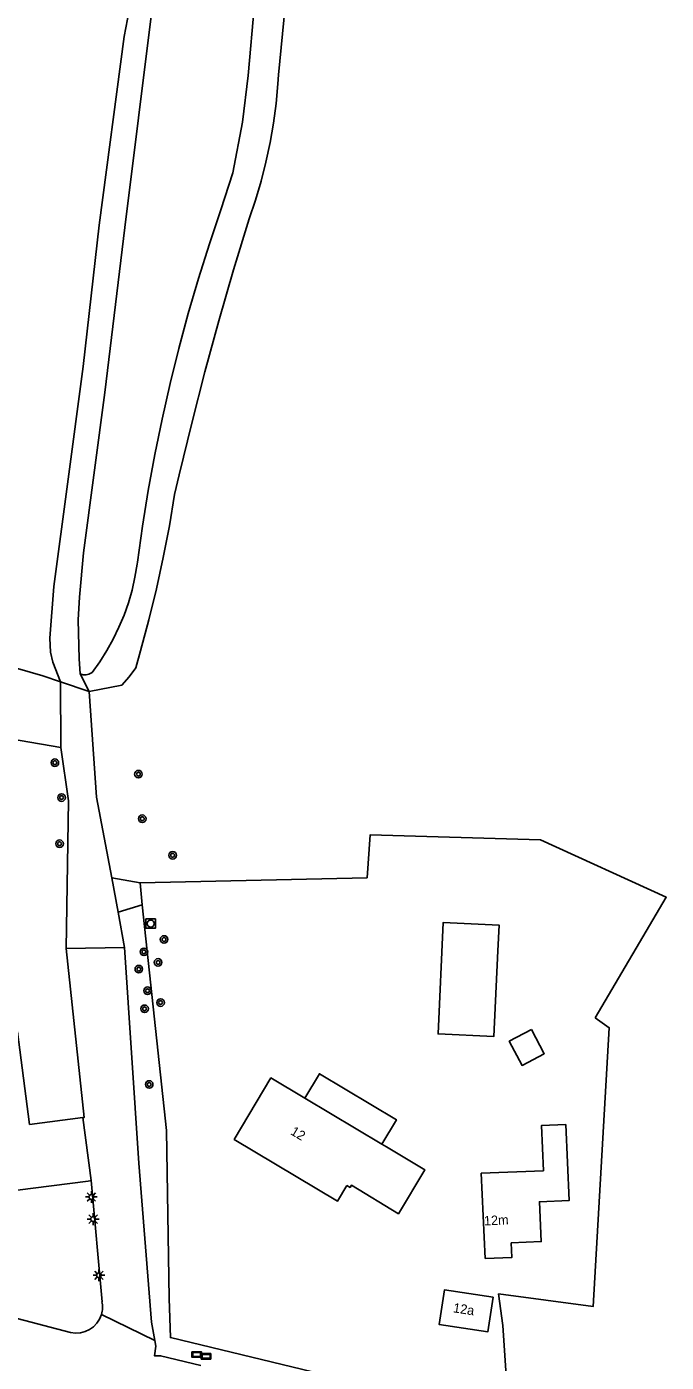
# Model space of a CAD drawing. Extents: x 137000 to 140001, y 403500 to 406000.
# Drawn here: x 138474.3 to 138542, y 405655.3 to 405796.6 of the extents above; entities that cross this region are included whole.
import ezdxf

# ---------------------------------------------------------------- set-up
doc = ezdxf.new("R2010")
doc.units = 0
for name, color, linetype in [('gg-afsc-erfafscheiding', 7, 'Continuous'), ('gg-anno-huisnummerreeks BGT', 7, 'Continuous'), ('gg-bbg-bijgebouw', 7, 'Continuous'), ('gg-bbg-hoofdgebouw', 7, 'Continuous'), ('gg-bbg-luifel en loopbrug', 7, 'Continuous'), ('gg-knt-verharding', 7, 'Continuous'), ('gt-grn-groengrens', 7, 'Continuous'), ('gt-grn-groengrens NZ', 7, 'Continuous'), ('gt-grn-weggrens', 7, 'Continuous'), ('gt-symb-boom', 7, 'Continuous'), ('gt-symb-informatiebord', 7, 'Continuous'), ('gt-symb-lichtmast', 7, 'Continuous'), ('gt-symb-rioolschacht', 7, 'Continuous'), ('gx-grn-maaiveld', 7, 'Continuous')]:
    doc.layers.add(name, color=color, linetype=linetype)

# ---------------------------------------------------------------- blocks, each defined once
blk = doc.blocks.new('gt0-IBORD')
at = {"layer": 'gt-symb-informatiebord'}
blk.add_lwpolyline([(-0.5, 0.29), (-0.5, -0.29), (0.5, -0.29), (0.5, 0.29), (-0.5, 0.29)], dxfattribs=at)
blk.add_lwpolyline([(-0.42, -0.21), (0.42, -0.21), (0.42, 0.21), (-0.42, 0.21)], close=True, dxfattribs=at)
blk = doc.blocks.new('gt0-LMAST')
at = {"layer": 'gt-symb-lichtmast'}
for p, q in [((-0.18, 0.17), (-0.45, 0.44)), ((-0.01, 0.25), (-0.01, 0.62)), ((0.17, 0.17), (0.44, 0.44)), ((-0.26, 0), (-0.63, 0)), ((-0.18, -0.18), (-0.45, -0.45)), ((-0.01, -0.25), (-0.01, -0.63)), ((0.44, -0.45), (0.17, -0.18)), ((0.24, 0), (0.62, 0))]:
    blk.add_line(p, q, dxfattribs=at)
blk.add_circle((-0.01, 0), 0.25, dxfattribs=at)
blk = doc.blocks.new('gt0-BOOM')
at = {"layer": 'gt-symb-boom'}
for radius in [0.4, 0.2]:
    blk.add_circle((0, 0), radius, dxfattribs=at)
blk = doc.blocks.new('gt0-RS')
at = {"layer": 'gt-symb-rioolschacht'}
blk.add_lwpolyline([(-0.5, -0.5), (0.5, -0.5), (0.5, 0.5), (-0.5, 0.5)], close=True, dxfattribs=at)
blk.add_circle((0, 0), 0.375, dxfattribs=at)

msp = doc.modelspace()

# ---------------------------------------------------------------- linework, layer by layer
at = {"layer": 'gg-afsc-erfafscheiding'}
msp.add_line((138486.33, 405706.01), (138486.54, 405703.68), dxfattribs=at)
for points in [[(138431.55, 405686.42), (138430.73, 405691.32), (138432.04, 405696.3), (138433.12, 405700.81), (138433.36, 405702.15), (138433.12, 405705.77), (138432.66, 405708.47), (138432.93, 405711.45), (138433.97, 405715.93), (138437.22, 405720.74), (138440.96, 405723.28), (138453.34, 405724.56), (138477.96, 405720.34)], [(138534.45, 405691.71), (138541.98, 405704.49), (138528.68, 405710.57), (138510.65, 405711.08), (138510.33, 405706.55), (138486.33, 405706.01)], [(138486.54, 405703.68), (138489.13, 405679.79), (138489.39, 405662.02), (138489.53, 405657.88), (138510.97, 405652.71)], [(138534.45, 405691.71), (138535.94, 405690.68), (138534.23, 405661.15), (138524.24, 405662.49)], [(138525.36, 405649.07), (138524.7, 405659.15), (138524.24, 405662.49)]]:
    msp.add_lwpolyline(points, dxfattribs=at)
at = {"layer": 'gg-bbg-bijgebouw'}
for points in [[(138524.16, 405698.8), (138523.75, 405689.75), (138517.85, 405690.02), (138518.39, 405701.82), (138524.29, 405701.55), (138524.16, 405698.8)], [(138527.71, 405690.49), (138529.07, 405687.93), (138526.73, 405686.68), (138525.37, 405689.24), (138527.71, 405690.49)]]:
    msp.add_lwpolyline(points, dxfattribs=at)
at = {"layer": 'gg-bbg-hoofdgebouw'}
for p, q in [((138511.9, 405678.35), (138503.75, 405683.22)), ((138480.27, 405681.18), (138481.15, 405674.49))]:
    msp.add_line(p, q, dxfattribs=at)
for points in [[(138481.15, 405674.49), (138480.83, 405674.45), (138469.46, 405672.97), (138469.72, 405670.99), (138465.26, 405670.4), (138465, 405672.39), (138456.09, 405671.22), (138453.9, 405687.96), (138454.75, 405688.07), (138454.63, 405688.96), (138454.33, 405688.93), (138453.54, 405694.97), (138465.4, 405696.52), (138472.02, 405697.38), (138472.81, 405691.33), (138471.87, 405691.2), (138472.02, 405690.06), (138473.35, 405690.24), (138474.63, 405680.44), (138480.27, 405681.18)], [(138503.75, 405683.22), (138500.17, 405685.36), (138496.28, 405678.86), (138507.22, 405672.33), (138508.2, 405673.97)], [(138522.82, 405666.24), (138525.66, 405666.37), (138525.59, 405667.89), (138528.76, 405668.03), (138528.56, 405672.26), (138531.71, 405672.4), (138531.35, 405680.43), (138528.79, 405680.33), (138528.98, 405675.53), (138522.41, 405675.27), (138522.82, 405666.24)], [(138508.2, 405673.97), (138508.54, 405673.77), (138508.68, 405674.01), (138513.65, 405670.99), (138516.43, 405675.64), (138512.39, 405678.06), (138511.9, 405678.35)], [(138523.66, 405662.14), (138518.52, 405662.92), (138517.95, 405659.27), (138523.1, 405658.48), (138523.66, 405662.14)]]:
    msp.add_lwpolyline(points, dxfattribs=at)
at = {"layer": 'gg-bbg-luifel en loopbrug'}
msp.add_lwpolyline([(138511.9, 405678.35), (138513.44, 405680.93), (138505.29, 405685.8), (138503.75, 405683.22)], dxfattribs=at)
at = {"layer": 'gg-knt-verharding'}
for p, q in [((138480.94, 405726.27), (138477.92, 405727.28)), ((138480, 405728.14), (138480.94, 405726.27)), ((138484, 405702.9), (138483.32, 405706.55)), ((138484.69, 405699.18), (138484, 405702.9)), ((138484.69, 405699.18), (138478.49, 405699.08)), ((138481.15, 405674.49), (138482.3, 405661.67)), ((138472.67, 405660.08), (138478.98, 405658.41)), ((138482.23, 405660.32), (138487.89, 405657.57))]:
    msp.add_line(p, q, dxfattribs=at)
for points in [[(138480.27, 405681.18), (138480.42, 405681.19), (138478.49, 405699.08)], [(138487.89, 405657.57), (138487.53, 405659.52), (138486.2, 405676.34), (138484.69, 405699.18)], [(138492.74, 405654.93), (138488.49, 405655.96), (138487.85, 405655.94), (138488, 405656.95), (138487.89, 405657.57)]]:
    msp.add_lwpolyline(points, dxfattribs=at)
for centre, radius, start, end in [((138479.57, 405661.12), 2.78, 343.3166, 11.5167), ((138479.58, 405661.12), 2.77, 257.4446, 343.2739)]:
    msp.add_arc(centre, radius, start, end, dxfattribs=at)
at = {"layer": 'gt-grn-groengrens'}
msp.add_lwpolyline([(138373.64, 405757.58), (138476.03, 405727.91), (138477.92, 405727.28)], dxfattribs=at)
at = {"layer": 'gt-grn-groengrens NZ'}
msp.add_line((138483.32, 405706.55), (138486.33, 405706.01), dxfattribs=at)
at = {"layer": 'gt-grn-weggrens'}
msp.add_line((138484, 405702.9), (138486.54, 405703.68), dxfattribs=at)
at = {"layer": 'gx-grn-maaiveld'}
msp.add_line((138477.96, 405720.34), (138477.92, 405727.28), dxfattribs=at)
for points in [[(138477.92, 405727.28), (138477.08, 405729.38), (138476.86, 405730.43), (138476.77, 405731.92), (138477.19, 405737.4), (138478.65, 405748.23), (138480.29, 405760.66), (138482.01, 405775.64), (138484.64, 405795.61), (138485.69, 405801.13), (138489.95, 405817.8), (138494.25, 405836.19), (138500.42, 405863.55), (138505.03, 405882.67), (138509.48, 405899), (138514.17, 405914.96), (138519.47, 405934.58), (138526.93, 405959.19), (138532.1, 405977.85), (138534.11, 405985.54), (138537.9, 405998.75), (138538.28, 406000)], [(138480, 405728.14), (138479.89, 405729.72), (138479.79, 405733.87), (138479.91, 405736.27), (138480.33, 405740.95), (138482.58, 405757.92), (138484.7, 405775.38), (138487.6, 405798.61), (138492.81, 405819.24), (138496.9, 405837.24), (138501.92, 405857.44), (138503.46, 405865.82), (138504.47, 405870.66), (138505.66, 405874.92), (138510.58, 405893.66), (138518.46, 405921.11), (138524.63, 405942.49), (138529.73, 405959.98), (138533.05, 405971.51), (138535.42, 405980.71), (138538.64, 405993.55), (138540.61, 406000)], [(138480.94, 405726.27), (138484.41, 405726.94), (138485.18, 405727.81), (138485.86, 405728.79), (138486.37, 405730.58), (138487.25, 405733.86), (138488.05, 405737.15), (138488.77, 405740.46), (138489.42, 405743.79), (138489.98, 405747.13), (138490.46, 405749.2), (138491.79, 405754.66), (138493.19, 405760.1), (138494.66, 405765.51), (138496.22, 405770.91), (138497.85, 405776.29), (138498.52, 405778.27), (138499.12, 405780.28), (138499.63, 405782.32), (138500.07, 405784.37), (138500.43, 405786.43), (138500.71, 405788.51), (138500.91, 405790.6), (138500.98, 405791.56), (138502.27, 405804.97)], [(138480, 405728.14), (138480.3, 405728.05), (138480.61, 405728.04), (138480.91, 405728.11), (138481.18, 405728.25), (138481.24, 405728.29), (138482.05, 405729.42), (138482.8, 405730.6), (138483.48, 405731.81), (138484.09, 405733.07), (138484.63, 405734.35), (138485.09, 405735.67), (138485.48, 405737.01), (138485.78, 405738.36), (138486.01, 405739.74), (138486.04, 405739.96), (138486.58, 405743.77), (138487.19, 405747.56), (138487.88, 405751.34), (138488.65, 405755.11), (138489.49, 405758.86), (138490.42, 405762.59), (138491.42, 405766.3), (138492.5, 405769.99), (138493.65, 405773.65), (138494.88, 405777.26), (138496.15, 405781.16), (138497.16, 405786.53), (138497.77, 405791.47), (138498.42, 405799.02)], [(138483.32, 405706.55), (138481.73, 405715.1), (138480.94, 405726.27)], [(138478.49, 405699.08), (138478.76, 405714.68), (138477.96, 405720.34)]]:
    msp.add_lwpolyline(points, dxfattribs=at)

# ---------------------------------------------------------------- block references
at = {"layer": 'gt-symb-boom'}
for p in [(138477.31, 405718.73), (138486.15, 405717.52), (138478.02, 405715.04), (138486.56, 405712.8), (138477.81, 405710.16), (138489.77, 405708.93), (138488.86, 405700.02), (138486.73, 405698.71), (138488.23, 405697.59), (138486.19, 405696.88), (138487.11, 405694.59), (138488.49, 405693.34), (138486.8, 405692.68), (138487.29, 405684.67)]:
    msp.add_blockref('gt0-BOOM', p, dxfattribs=at)
at = {"layer": 'gt-symb-informatiebord'}
for p in [(138492.31, 405656.09), (138493.3, 405655.89)]:
    msp.add_blockref('gt0-IBORD', p, dxfattribs=at)
at = {"layer": 'gt-symb-lichtmast'}
for p in [(138481.18, 405672.76), (138481.37, 405670.42), (138481.98, 405664.47)]:
    msp.add_blockref('gt0-LMAST', p, dxfattribs=at)
at = {"layer": 'gt-symb-rioolschacht'}
msp.add_blockref('gt0-RS', (138487.45, 405701.7), dxfattribs=at)

# ---------------------------------------------------------------- texts
at = {"layer": 'gg-anno-huisnummerreeks BGT'}
for s, rotation, p in [('12', 329.2, (138502.15, 405679.44)), ('12m', 2.6, (138522.72, 405669.74)), ('12a', 351.3, (138519.39, 405660.56))]:
    msp.add_text(s, height=1, rotation=rotation, dxfattribs=at).set_placement(p)

doc.saveas('drawing.dxf')
